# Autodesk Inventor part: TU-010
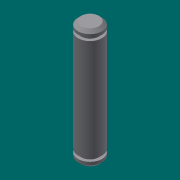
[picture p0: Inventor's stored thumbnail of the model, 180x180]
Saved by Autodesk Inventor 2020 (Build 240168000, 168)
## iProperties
Created: 2002-07
Part Number: TU-010
Document SubType Name: Modeling
Designer: PN
Description: Short Pin
Density: 1 g/cm^3
Mass: 1.9436 g
Surface Area: 11.4919 cm^2
Volume: 1.9436 cm^3
Material: Generic
Appearance: Default
Control State: 0
Master: False
Checked Out: False
Shininess: 64.0
Angle Display Precision: 2
Document Length Units: 11269
Document Angle Units: 11279
Document Time Units: 11290
Document Mass Units: 11286
Document Length Units Precision: 3
Document Angle Units Precision: 2
Compacted: True
LENGTH: 1.000 in
Density: 0.0
Volumn: 0.0
Area: 0.0
PropertySet Name: Model Information
Author: PN
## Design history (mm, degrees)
sketch "Sketch1"
  geometry: L1 (0, 20)-(3, 20); L2 (3, 17)-(4, 17); L3 (3, 18)-(3, 17); L4 (4, 18)-(3, 18); L5 (4, 19)-(4, 18); L6 (3, 20)-(4, 19); L7 (4, 17)-(4, -17); L8 (4, -17)-(3, -17); L9 (3, -17)-(3, -18); L10 (3, -18)-(4, -18); L11 (4, -18)-(4, -19); L12 (4, -19)-(3, -20); L13 (0, 20)-(0, -20); L14 (0, -20)-(3, -20); 1 further point
  constraints: 28 end point, 6 parallel, 5 perpendicular, 1 horizontal, 1 midpoint, 1 vertical
  dimensions: "d4" = 35 distance between parallel lines of L4 L8; "d5" = 1 distance between parallel lines of L4 L2; "d6" = 36 distance between parallel lines of L4 L10; "d7" = 2 distance between parallel lines of L4 L1
revolve "Revolution1" sketch "Sketch1" stored, may be unused: angle "d19" = 90 deg
body "Solid1"
other parameters: "LENGTH" = 25.4 [user parameter]
